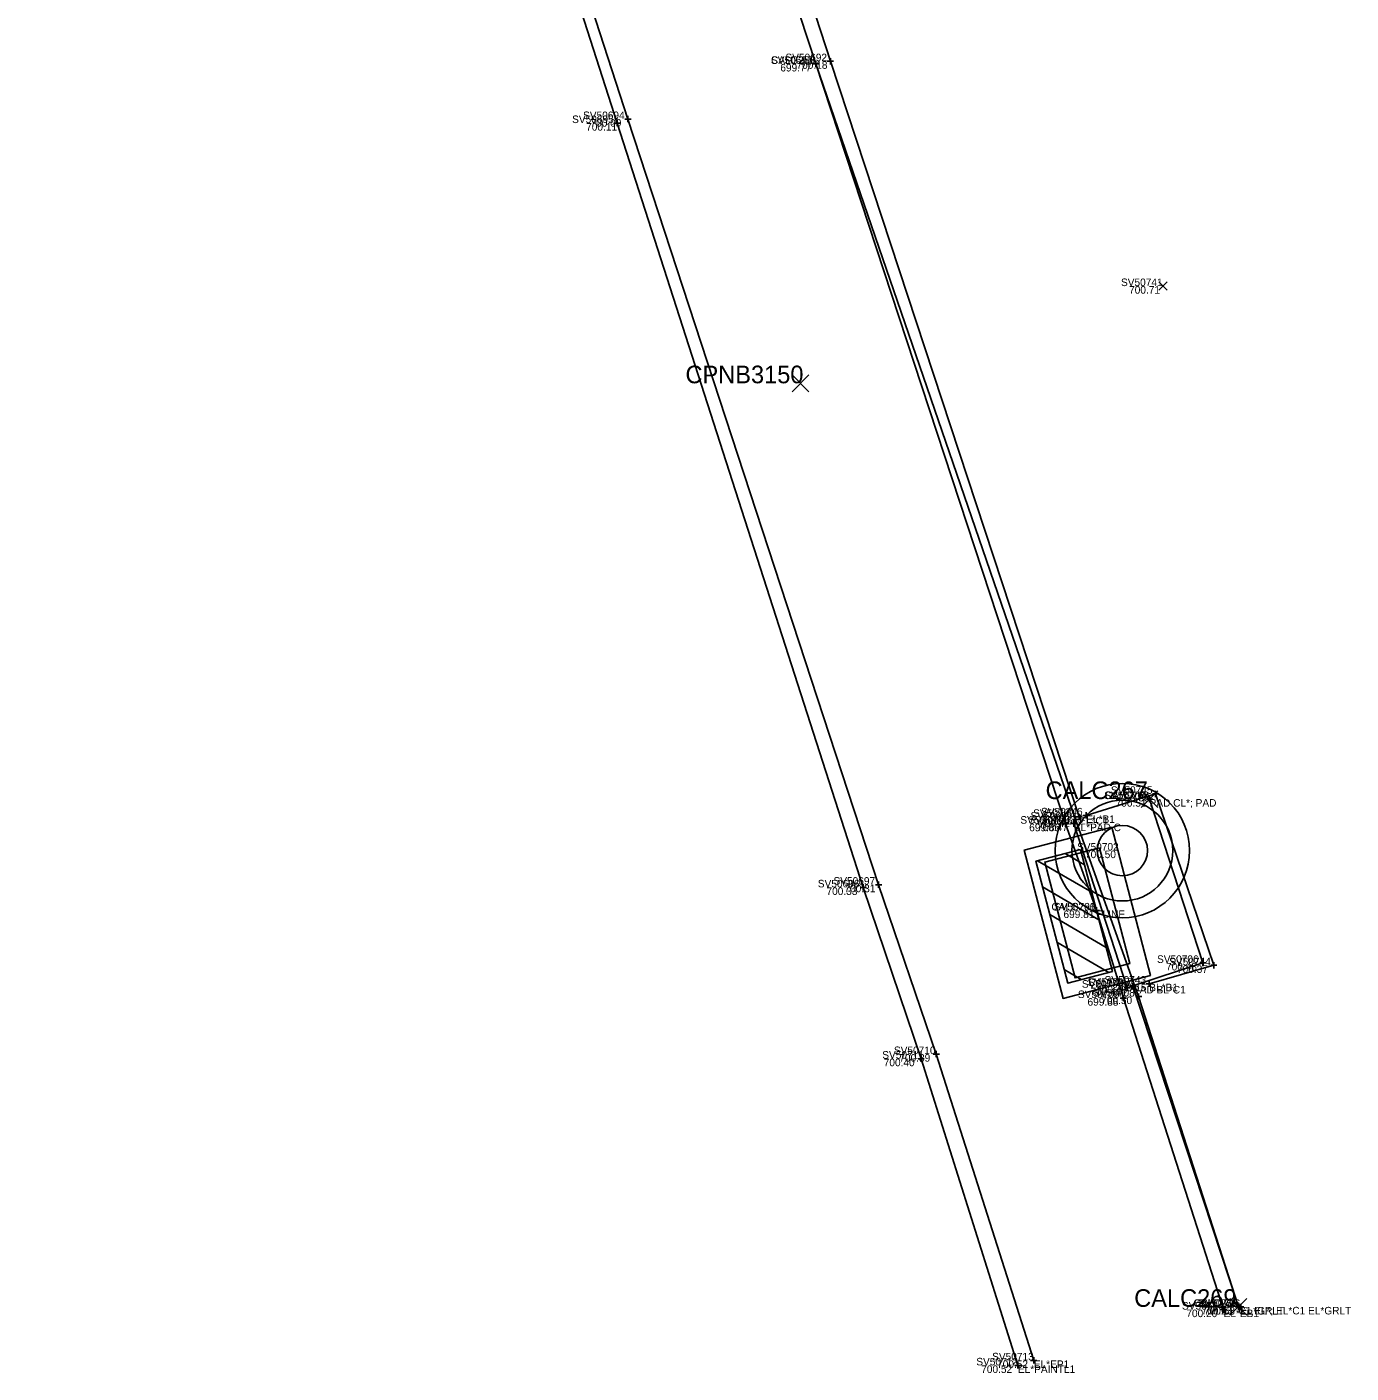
# Model space of a CAD drawing. Extents: x 182090 to 1832865, y 706265 to 714392.
# Drawn here: x 1823784.5 to 1823837.1, y 710644.4 to 710697.9 of the extents above; entities that cross this region are included whole.
import ezdxf

# ---------------------------------------------------------------- set-up
doc = ezdxf.new("R2010")
doc.units = 0
for name, color, linetype in [('DR_X_Cells', 7, 'Continuous'), ('GK_Drainage_Nodes', 7, 'Continuous'), ('GK_Visualization', 7, 'Continuous'), ('PV_X_Curb', 7, 'Continuous'), ('PV_X_EOP', 7, 'Continuous'), ('PV_X_Shoulder', 7, 'Continuous'), ('RD_X_Concrete_Pad', 7, 'Continuous'), ('RD_X_GR_Lt', 7, 'Continuous'), ('SV_X_Break_Lines', 7, 'Continuous'), ('SV_X_Random_Point', 7, 'Continuous'), ('SV_X_Shot_Marker', 7, 'Continuous'), ('SV_X_Text_Comment', 7, 'Continuous'), ('SV_X_Text_Elevation', 7, 'Continuous'), ('SV_X_Text_Name', 7, 'Continuous')]:
    doc.layers.add(name, color=color, linetype=linetype)

msp = doc.modelspace()

# ---------------------------------------------------------------- linework, layer by layer
at = {"layer": 'DR_X_Cells'}
for p, q in [((1823824.655, 710664.779), (1823826.8, 710663.527)), ((1823825.752, 710665.066), (1823826.515, 710664.62)), ((1823824.85, 710663.739), (1823827.086, 710662.434)), ((1823825.136, 710662.646), (1823827.372, 710661.34)), ((1823825.421, 710661.553), (1823827.482, 710660.35)), ((1823825.707, 710660.46), (1823826.386, 710660.063))]:
    msp.add_line(p, q, dxfattribs=at)
for points in [[(1823827.592, 710666.106), (1823829.129, 710660.22), (1823825.662, 710659.314), (1823824.124, 710665.2)], [(1823826.357, 710665.224), (1823827.621, 710660.386), (1823825.847, 710659.923), (1823824.583, 710664.76)], [(1823827.114, 710665.292), (1823828.315, 710660.697), (1823826.138, 710660.128), (1823824.937, 710664.724)]]:
    msp.add_lwpolyline(points, close=True, dxfattribs=at)
for radius in [2.667, 2, 1]:
    msp.add_circle((1823828.017, 710665.182), radius, dxfattribs=at)
at = {"layer": 'GK_Drainage_Nodes'}
for p, q in [((1823828.017, 710667.182), (1823828.017, 710667.182)), ((1823826.026, 710665.008), (1823826.026, 710665.008)), ((1823828.017, 710665.182), (1823828.017, 710665.182)), ((1823828.017, 710665.182), (1823828.017, 710665.182)), ((1823828.017, 710665.182), (1823828.017, 710665.182)), ((1823828.017, 710663.182), (1823828.017, 710663.182)), ((1823828.36, 710663.163), (1823828.36, 710663.163)), ((1823826.626, 710662.71), (1823826.626, 710662.71)), ((1823826.989, 710662.805), (1823826.989, 710662.805)), ((1823826.989, 710662.805), (1823826.989, 710662.805)), ((1823827.715, 710662.995), (1823827.715, 710662.995)), ((1823824.893, 710662.257), (1823824.893, 710662.257)), ((1823825.538, 710662.426), (1823825.538, 710662.426)), ((1823827.227, 710660.412), (1823827.227, 710660.412))]:
    msp.add_line(p, q, dxfattribs=at)
msp.add_circle((1823828.017, 710665.182), 2, dxfattribs=at)
at = {"layer": 'GK_Visualization'}
for p, q in [((1823814.908, 710683.391), (1823815.574, 710684.059)), ((1823814.908, 710684.059), (1823815.574, 710683.391)), ((1823828.764, 710666.891), (1823829.43, 710667.559)), ((1823828.764, 710667.559), (1823829.43, 710666.891)), ((1823832.287, 710646.742), (1823832.953, 710647.41)), ((1823832.287, 710647.41), (1823832.953, 710646.742))]:
    msp.add_line(p, q, dxfattribs=at)
at = {"layer": 'PV_X_Curb'}
msp.add_line((1823828.436, 710659.812), (1823832.62, 710647.076), dxfattribs=at)
msp.add_lwpolyline([(1823807.913, 710722.651), (1823816.428, 710696.503), (1823826.301, 710666.518)], dxfattribs=at)
at = {"layer": 'PV_X_EOP'}
msp.add_lwpolyline([(1823743.92, 710890.39), (1823755.131, 710855.835), (1823761.886, 710835.437), (1823768.207, 710815.966), (1823773.518, 710800.011), (1823786.939, 710759.023), (1823798.833, 710722.493), (1823807.966, 710694.05), (1823817.736, 710663.721), (1823820.032, 710656.924), (1823823.87, 710644.753)], dxfattribs=at)
at = {"layer": 'PV_X_Shoulder'}
for points in [[(1823751.956, 710892.127), (1823763.015, 710858.494), (1823769.826, 710837.558), (1823776.247, 710818.024), (1823781.298, 710802.04), (1823794.561, 710761.086), (1823806.444, 710725.027), (1823815.858, 710696.398), (1823825.756, 710666.248), (1823826.989, 710662.805), (1823828.055, 710659.329), (1823832.034, 710646.968)], [(1823744.277, 710890.408), (1823755.488, 710855.959), (1823762.24, 710835.51), (1823768.533, 710816.11), (1823773.88, 710800.088), (1823787.26, 710759.125), (1823799.186, 710722.602), (1823808.397, 710694.208), (1823818.34, 710663.828), (1823820.63, 710657.106), (1823824.501, 710644.952)]]:
    msp.add_lwpolyline(points, dxfattribs=at)
at = {"layer": 'RD_X_Concrete_Pad'}
msp.add_lwpolyline([(1823826.088, 710666.253), (1823828.209, 710659.74), (1823828.436, 710659.812), (1823831.211, 710660.724), (1823829.097, 710667.225)], dxfattribs=at)
at = {"layer": 'RD_X_GR_Lt'}
msp.add_lwpolyline([(1823806.444, 710725.027), (1823815.858, 710696.398), (1823826.16, 710666.412), (1823828.66, 710659.391), (1823832.62, 710647.076)], dxfattribs=at)
at = {"layer": 'SV_X_Break_Lines'}
msp.add_lwpolyline([(1823829.084, 710659.9), (1823831.646, 710660.629), (1823829.335, 710667.432), (1823826.582, 710666.577)], dxfattribs=at)
at = {"layer": 'SV_X_Random_Point'}
for p, q in [((1823829.46, 710687.414), (1823829.794, 710687.748)), ((1823829.46, 710687.748), (1823829.794, 710687.414))]:
    msp.add_line(p, q, dxfattribs=at)
at = {"layer": 'SV_X_Shot_Marker'}
for p, q in [((1823815.733, 710696.398), (1823815.983, 710696.398)), ((1823815.733, 710696.398), (1823815.983, 710696.398)), ((1823815.858, 710696.523), (1823815.858, 710696.273)), ((1823815.858, 710696.523), (1823815.858, 710696.273)), ((1823815.858, 710696.398), (1823815.858, 710696.398)), ((1823815.858, 710696.398), (1823815.858, 710696.398)), ((1823816.303, 710696.503), (1823816.553, 710696.503)), ((1823816.428, 710696.628), (1823816.428, 710696.378)), ((1823816.428, 710696.503), (1823816.428, 710696.503)), ((1823807.966, 710694.175), (1823807.966, 710693.925)), ((1823808.272, 710694.208), (1823808.522, 710694.208)), ((1823808.397, 710694.333), (1823808.397, 710694.083)), ((1823808.397, 710694.208), (1823808.397, 710694.208)), ((1823807.841, 710694.05), (1823808.091, 710694.05)), ((1823807.966, 710694.05), (1823807.966, 710694.05)), ((1823829.097, 710667.35), (1823829.097, 710667.1)), ((1823829.097, 710667.35), (1823829.097, 710667.1)), ((1823829.21, 710667.432), (1823829.46, 710667.432)), ((1823829.335, 710667.557), (1823829.335, 710667.307)), ((1823829.335, 710667.432), (1823829.335, 710667.432)), ((1823828.972, 710667.225), (1823829.222, 710667.225)), ((1823828.972, 710667.225), (1823829.222, 710667.225)), ((1823829.097, 710667.225), (1823829.097, 710667.225)), ((1823829.097, 710667.225), (1823829.097, 710667.225)), ((1823825.756, 710666.373), (1823825.756, 710666.123)), ((1823826.035, 710666.412), (1823826.285, 710666.412)), ((1823826.088, 710666.378), (1823826.088, 710666.128)), ((1823826.16, 710666.537), (1823826.16, 710666.287)), ((1823826.16, 710666.412), (1823826.16, 710666.412)), ((1823826.176, 710666.518), (1823826.426, 710666.518)), ((1823826.301, 710666.643), (1823826.301, 710666.393)), ((1823826.301, 710666.518), (1823826.301, 710666.518)), ((1823826.457, 710666.577), (1823826.707, 710666.577)), ((1823826.582, 710666.702), (1823826.582, 710666.452)), ((1823826.582, 710666.577), (1823826.582, 710666.577)), ((1823825.631, 710666.248), (1823825.881, 710666.248)), ((1823825.756, 710666.248), (1823825.756, 710666.248)), ((1823825.963, 710666.253), (1823826.213, 710666.253)), ((1823826.088, 710666.253), (1823826.088, 710666.253)), ((1823817.611, 710663.721), (1823817.861, 710663.721)), ((1823817.736, 710663.846), (1823817.736, 710663.596)), ((1823817.736, 710663.721), (1823817.736, 710663.721)), ((1823818.215, 710663.828), (1823818.465, 710663.828)), ((1823818.34, 710663.953), (1823818.34, 710663.703)), ((1823818.34, 710663.828), (1823818.34, 710663.828)), ((1823826.864, 710662.805), (1823827.114, 710662.805)), ((1823826.989, 710662.93), (1823826.989, 710662.68)), ((1823826.989, 710662.805), (1823826.989, 710662.805)), ((1823831.086, 710660.724), (1823831.336, 710660.724)), ((1823831.211, 710660.849), (1823831.211, 710660.599)), ((1823831.211, 710660.724), (1823831.211, 710660.724)), ((1823831.521, 710660.629), (1823831.771, 710660.629)), ((1823831.646, 710660.754), (1823831.646, 710660.504)), ((1823831.646, 710660.629), (1823831.646, 710660.629)), ((1823828.209, 710659.865), (1823828.209, 710659.615)), ((1823828.436, 710659.937), (1823828.436, 710659.687)), ((1823828.436, 710659.937), (1823828.436, 710659.687)), ((1823828.959, 710659.9), (1823829.209, 710659.9)), ((1823829.084, 710660.025), (1823829.084, 710659.775)), ((1823829.084, 710659.9), (1823829.084, 710659.9)), ((1823828.055, 710659.454), (1823828.055, 710659.204)), ((1823828.084, 710659.74), (1823828.334, 710659.74)), ((1823828.209, 710659.74), (1823828.209, 710659.74)), ((1823828.311, 710659.812), (1823828.561, 710659.812)), ((1823828.311, 710659.812), (1823828.561, 710659.812)), ((1823828.436, 710659.812), (1823828.436, 710659.812)), ((1823828.436, 710659.812), (1823828.436, 710659.812)), ((1823828.535, 710659.391), (1823828.785, 710659.391)), ((1823828.66, 710659.516), (1823828.66, 710659.266)), ((1823828.66, 710659.391), (1823828.66, 710659.391)), ((1823827.93, 710659.329), (1823828.18, 710659.329)), ((1823828.055, 710659.329), (1823828.055, 710659.329)), ((1823820.63, 710657.231), (1823820.63, 710656.981)), ((1823819.907, 710656.924), (1823820.157, 710656.924)), ((1823820.032, 710657.049), (1823820.032, 710656.799)), ((1823820.032, 710656.924), (1823820.032, 710656.924)), ((1823820.505, 710657.106), (1823820.755, 710657.106)), ((1823820.63, 710657.106), (1823820.63, 710657.106)), ((1823832.034, 710647.093), (1823832.034, 710646.843)), ((1823832.495, 710647.076), (1823832.745, 710647.076)), ((1823832.495, 710647.076), (1823832.745, 710647.076)), ((1823832.495, 710647.076), (1823832.745, 710647.076)), ((1823832.592, 710647.071), (1823832.842, 710647.071)), ((1823832.62, 710647.201), (1823832.62, 710646.951)), ((1823832.62, 710647.201), (1823832.62, 710646.951)), ((1823832.62, 710647.201), (1823832.62, 710646.951)), ((1823832.62, 710647.076), (1823832.62, 710647.076)), ((1823832.62, 710647.076), (1823832.62, 710647.076)), ((1823832.62, 710647.076), (1823832.62, 710647.076)), ((1823832.717, 710647.196), (1823832.717, 710646.946)), ((1823832.717, 710647.071), (1823832.717, 710647.071)), ((1823831.909, 710646.968), (1823832.159, 710646.968)), ((1823832.034, 710646.968), (1823832.034, 710646.968)), ((1823824.376, 710644.952), (1823824.626, 710644.952)), ((1823824.501, 710645.077), (1823824.501, 710644.827)), ((1823824.501, 710644.952), (1823824.501, 710644.952)), ((1823823.745, 710644.753), (1823823.995, 710644.753)), ((1823823.87, 710644.878), (1823823.87, 710644.628)), ((1823823.87, 710644.753), (1823823.87, 710644.753))]:
    msp.add_line(p, q, dxfattribs=at)

# ---------------------------------------------------------------- texts
at = {"layer": 'GK_Visualization'}
for s, p in [('CPNB3150', (1823810.678, 710683.725)), ('CALC267', (1823824.969, 710667.225)), ('CALC269', (1823828.486, 710647.076))]:
    msp.add_text(s, height=0.7, dxfattribs=at).set_placement(p)
at = {"layer": 'SV_X_Text_Comment'}
for s, p in [('PAD CL*; PAD', (1823829.097, 710666.925)), ('EL*C1', (1823826.301, 710666.218)), ('EL*B1', (1823826.582, 710666.277)), ('BL*PAD C', (1823826.088, 710665.953)), ('FLINE', (1823826.989, 710662.505)), ('BL*B1', (1823829.084, 710659.6)), ('PAD BL*C1', (1823828.436, 710659.512)), ('C1 EL*; EL*C1 EL*GRLT', (1823832.62, 710646.776)), ('EL*GRLT', (1823832.717, 710646.771)), ('EL*EB1', (1823832.034, 710646.668)), ('EL*EP1', (1823824.501, 710644.652)), ('EL*PAINTL1', (1823823.87, 710644.453))]:
    msp.add_text(s, height=0.3, dxfattribs=at).set_placement(p)
at = {"layer": 'SV_X_Text_Elevation'}
for s, p in [('699.77', (1823814.443, 710696.098)), ('699.77', (1823814.443, 710696.098)), ('700.18', (1823815.086, 710696.203)), ('700.11', (1823806.736, 710693.75)), ('700.09', (1823806.909, 710693.908)), ('700.71', (1823828.283, 710687.281)), ('700.38', (1823827.871, 710667.132)), ('700.51', (1823827.749, 710666.925)), ('700.51', (1823827.749, 710666.925)), ('700.42', (1823824.703, 710666.112)), ('700.46', (1823824.822, 710666.218)), ('700.15', (1823825.243, 710666.277)), ('699.86', (1823824.318, 710665.948)), ('700.47', (1823824.628, 710665.953)), ('700.50', (1823826.534, 710664.882)), ('700.33', (1823816.274, 710663.421)), ('700.31', (1823816.987, 710663.528)), ('699.81', (1823825.679, 710662.505)), ('699.81', (1823825.679, 710662.505)), ('700.48', (1823829.749, 710660.424)), ('700.37', (1823830.184, 710660.329)), ('700.15', (1823827.745, 710659.6)), ('699.88', (1823826.633, 710659.029)), ('700.44', (1823826.752, 710659.44)), ('700.48', (1823826.974, 710659.512)), ('700.48', (1823826.974, 710659.512)), ('700.50', (1823827.177, 710659.091)), ('700.40', (1823818.546, 710656.624)), ('700.39', (1823819.166, 710656.806)), ('700.63', (1823831.158, 710646.776)), ('700.63', (1823831.158, 710646.776)), ('700.63', (1823831.158, 710646.776)), ('700.58', (1823831.257, 710646.771)), ('700.20', (1823830.555, 710646.668)), ('700.52', (1823823.046, 710644.652)), ('700.52', (1823822.415, 710644.453))]:
    msp.add_text(s, height=0.3, dxfattribs=at).set_placement(p)
at = {"layer": 'SV_X_Text_Name'}
for s, p in [('SV50692', (1823814.645, 710696.503)), ('SV50693', (1823814.072, 710696.398)), ('CALC256', (1823814.075, 710696.398)), ('SV50695', (1823806.18, 710694.05)), ('SV50694', (1823806.614, 710694.208)), ('SV50741', (1823827.962, 710687.581)), ('SV50707', (1823827.297, 710667.225)), ('CALC268', (1823827.325, 710667.225)), ('SV50745', (1823827.561, 710667.432)), ('SV50700', (1823824.475, 710666.518)), ('SV50746', (1823824.789, 710666.577)), ('SV50698', (1823823.968, 710666.248)), ('SV50703', (1823824.288, 710666.253)), ('SV50699', (1823824.372, 710666.412)), ('SV50702', (1823826.219, 710665.182)), ('SV50696', (1823815.931, 710663.721)), ('SV50697', (1823816.554, 710663.828)), ('CALC266', (1823825.201, 710662.805)), ('SV50701', (1823825.298, 710662.805)), ('SV50706', (1823829.392, 710660.724)), ('SV50744', (1823829.874, 710660.629)), ('SV50704', (1823826.411, 710659.74)), ('SV50705', (1823826.636, 710659.812)), ('CALC247', (1823826.669, 710659.812)), ('SV50743', (1823827.31, 710659.9)), ('SV50709', (1823826.253, 710659.329)), ('SV50708', (1823826.858, 710659.391)), ('SV50711', (1823818.488, 710656.924)), ('SV50710', (1823818.951, 710657.106)), ('SV50714', (1823830.383, 710646.968)), ('CALC270', (1823830.834, 710647.076)), ('CALC257', (1823830.856, 710647.076)), ('SV50715', (1823830.967, 710647.076)), ('SV50716', (1823831.045, 710647.071)), ('SV50712', (1823822.219, 710644.753)), ('SV50713', (1823822.848, 710644.952))]:
    msp.add_text(s, height=0.3, dxfattribs=at).set_placement(p)

doc.saveas('drawing.dxf')
